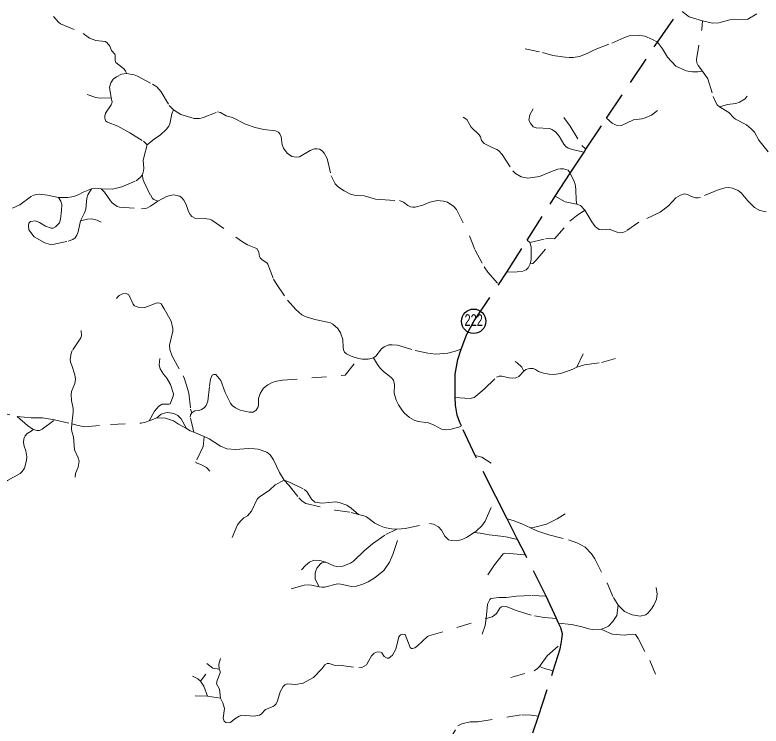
# Model space of a CAD drawing. Extents: x 220.8 to 246.7, y 7287.6 to 7315.8.
# Drawn here: x 238.74 to 243.82, y 7293.59 to 7298.43 of the extents above; entities that cross this region are included whole.
import ezdxf
from ezdxf.enums import TextEntityAlignment as Align

# ---------------------------------------------------------------- set-up
doc = ezdxf.new("R2010")
doc.units = 0
doc.header["$LTSCALE"] = 0.032
for name, pattern in [('DOTTED', [1.5, 0.3, -1.2]), ('LONG_DASHED', [7.5, 6, -1.5]), ('MEDIUM_DASHED', [4.5, 3, -1.5])]:
    doc.linetypes.add(name, pattern=pattern)
for name, color, linetype, lineweight in [('13', 7, 'Continuous', 25), ('4', 7, 'LONG_DASHED', 25), ('6', 7, 'MEDIUM_DASHED', 13), ('7', 7, 'DOTTED', 13)]:
    doc.layers.add(name, color=color, linetype=linetype, lineweight=lineweight)
doc.layers.add('61', color=7, linetype='Continuous')

msp = doc.modelspace()

# ---------------------------------------------------------------- linework, layer by layer
at = {"layer": '13'}
msp.add_circle((241.8611, 7296.3455), 0.083, dxfattribs=at)
at = {"layer": '4'}
msp.add_lwpolyline([(242.2645, 7293.5438), (242.3022, 7293.6576), (242.4029, 7293.9656), (242.4498, 7294.1165), (242.4567, 7294.1518), (242.4624, 7294.1805), (242.4649, 7294.2194), (242.4548, 7294.2595), (242.4398, 7294.2921), (242.4259, 7294.3221), (242.3548, 7294.4756), (242.2129, 7294.7565), (242.1598, 7294.8614), (242.0888, 7295.0017), (242.0123, 7295.1523), (241.8711, 7295.4321), (241.7772, 7295.6332), (241.7658, 7295.6577), (241.7495, 7295.7067), (241.7382, 7295.7757), (241.734, 7295.8278), (241.7344, 7295.9853), (241.7532, 7296.0857), (241.7753, 7296.1551), (241.8147, 7296.2576), (241.8649, 7296.348), (242.031, 7296.5946), (242.0862, 7296.68), (242.225, 7296.8973), (242.4158, 7297.1958), (242.5187, 7297.3535), (242.6137, 7297.4974), (242.626, 7297.516), (242.7662, 7297.7271), (243.1124, 7298.2445), (243.2485, 7298.4414)], dxfattribs=at)
at = {"layer": '6'}
for points in [[(243.2801, 7298.4546), (243.3292, 7298.417), (243.42, 7298.3897)], [(243.42, 7298.3897), (243.4865, 7298.3735), (243.5308, 7298.376), (243.6061, 7298.3965), (243.6389, 7298.4014), (243.7102, 7298.3989), (243.7282, 7298.4014), (243.7905, 7298.4383)], [(243.4199, 7298.0487), (243.3906, 7298.0859), (243.3814, 7298.1042), (243.3782, 7298.127), (243.4141, 7298.3319), (243.42, 7298.3897)], [(243.1124, 7298.2445), (243.1479, 7298.1994), (243.1811, 7298.1427), (243.2372, 7298.082), (243.3071, 7298.05), (243.3521, 7298.0442), (243.3886, 7298.0442), (243.4199, 7298.0487)], [(243.4199, 7298.0487), (243.4565, 7297.9952), (243.493, 7297.8745), (243.5087, 7297.8386), (243.5204, 7297.8184), (243.5357, 7297.8055), (243.598, 7297.7662), (243.632, 7297.7303), (243.645, 7297.7206), (243.72, 7297.6834), (243.7507, 7297.656), (243.7735, 7297.6331), (243.8042, 7297.5783), (243.8877, 7297.4713)], [(240.2175, 7297.7332), (240.3073, 7297.6864), (240.372, 7297.6647), (240.4324, 7297.6514), (240.5115, 7297.6419), (240.5311, 7297.6318), (240.5411, 7297.6202), (240.5496, 7297.6), (240.5565, 7297.5454), (240.5661, 7297.5226), (240.5899, 7297.4897), (240.6223, 7297.4664), (240.6551, 7297.4627), (240.6748, 7297.4653), (240.7464, 7297.5083), (240.7771, 7297.5183), (240.7951, 7297.5199), (240.8121, 7297.5157), (240.8301, 7297.5046), (240.8429, 7297.4902), (240.8641, 7297.4542), (240.8916, 7297.3359), (240.9182, 7297.2819), (240.9404, 7297.258), (240.9786, 7297.2331), (241.0263, 7297.2084), (241.0603, 7297.2023), (241.1149, 7297.2002), (241.1923, 7297.1774), (241.2236, 7297.1732), (241.3567, 7297.1668), (241.3826, 7297.1567), (241.4134, 7297.1339), (241.4304, 7297.1254), (241.4468, 7297.1217), (241.4632, 7297.1223), (241.5147, 7297.1366), (241.5619, 7297.1557), (241.6138, 7297.1679), (241.6557, 7297.1636), (241.6833, 7297.1562), (241.7252, 7297.126), (241.7443, 7297.1058), (241.8323, 7296.9271), (241.8705, 7296.829), (241.9325, 7296.7171), (241.958, 7296.68), (242.031, 7296.5946)], [(239.3238, 7297.2476), (239.4021, 7297.2451), (239.465, 7297.2594), (239.5631, 7297.3023), (239.5898, 7297.3242), (239.6061, 7297.3423), (239.609, 7297.3148), (239.6148, 7297.2962), (239.6598, 7297.2049), (239.674, 7297.1818), (239.6823, 7297.1741), (239.7099, 7297.163)], [(239.0333, 7297.1878), (239.0504, 7297.1628), (239.0555, 7297.1396), (239.0547, 7297.1002), (239.0478, 7297.0411), (239.0401, 7297.0162), (239.0136, 7296.9888), (238.9964, 7296.9802), (238.9827, 7296.9785), (238.945, 7296.9931), (238.9038, 7297.0179), (238.8764, 7297.0282), (238.8439, 7297.0239), (238.8319, 7297.0136), (238.8284, 7296.9982), (238.8327, 7296.9673), (238.867, 7296.9211), (238.9407, 7296.8791), (238.9707, 7296.8696), (238.993, 7296.8671), (239.1001, 7296.8902), (239.1318, 7296.9014), (239.1473, 7296.9142), (239.1575, 7296.9305), (239.1678, 7296.9545), (239.1838, 7297.0297), (239.2115, 7297.083), (239.2201, 7297.1088), (239.2261, 7297.1842), (239.233, 7297.2065), (239.2583, 7297.2465)], [(239.0333, 7297.1878), (239.0983, 7297.1879), (239.1373, 7297.1956), (239.1678, 7297.206), (239.2021, 7297.2251), (239.2583, 7297.2465)], [(239.2583, 7297.2465), (239.284, 7297.2508), (239.3238, 7297.2476)], [(239.3238, 7297.2476), (239.3461, 7297.2245), (239.388, 7297.1645), (239.4001, 7297.1519), (239.4336, 7297.1263), (239.4495, 7297.1216), (239.5999, 7297.1105), (239.6343, 7297.1156), (239.6604, 7297.1291), (239.7099, 7297.163)], [(243.8525, 7297.0897), (243.8094, 7297.0994), (243.7742, 7297.1203), (243.7279, 7297.1653), (243.6822, 7297.2195), (243.662, 7297.2358), (243.6248, 7297.2515), (243.5993, 7297.2554), (243.5726, 7297.2547), (243.5256, 7297.241), (243.4056, 7297.1882), (243.3899, 7297.1849), (243.371, 7297.1856), (243.3442, 7297.194), (243.3175, 7297.2084), (243.2947, 7297.2117), (243.2686, 7297.2038), (243.2385, 7297.1849), (243.187, 7297.1308), (243.1309, 7297.0884), (242.9867, 7297.0192), (242.8986, 7296.9592), (242.8778, 7296.95), (242.8634, 7296.9481), (242.838, 7296.952), (242.7832, 7296.9716), (242.729, 7296.9683), (242.7166, 7296.9709), (242.6996, 7296.9807), (242.6892, 7296.9898), (242.6664, 7297.0218), (242.6188, 7297.1017), (242.5887, 7297.1327), (242.5635, 7297.1424), (242.4837, 7297.1575), (242.4158, 7297.1958)], [(238.721, 7297.1162), (238.7692, 7297.1373), (238.8563, 7297.2006), (238.8839, 7297.2089), (238.903, 7297.2108), (238.9582, 7297.2032), (239.0333, 7297.1878)], [(239.7099, 7297.163), (239.7694, 7297.1943), (239.7936, 7297.2022), (239.8178, 7297.205), (239.8597, 7297.1971), (239.8737, 7297.1859), (239.8877, 7297.1687), (239.904, 7297.1407), (239.9198, 7297.0923), (239.9305, 7297.0723), (239.9426, 7297.0583), (239.9664, 7297.0453), (240.0441, 7297.0429), (240.0627, 7297.0406), (240.0772, 7297.0346), (240.2858, 7296.8865), (240.3203, 7296.8664), (240.3766, 7296.8441), (240.3855, 7296.838), (240.3971, 7296.8143), (240.4018, 7296.7854), (240.4069, 7296.777), (240.418, 7296.7659), (240.4548, 7296.7403), (240.46, 7296.7333), (240.4981, 7296.6313), (240.5154, 7296.602), (240.5922, 7296.4902), (240.6504, 7296.425), (240.6909, 7296.3887), (240.7128, 7296.3775), (240.7789, 7296.3579), (240.8823, 7296.3365), (240.9009, 7296.3267), (240.9349, 7296.2965), (240.9536, 7296.2667), (240.9694, 7296.2224), (240.9717, 7296.168), (240.9754, 7296.1503), (240.9824, 7296.1358), (240.9959, 7296.1232), (241.0267, 7296.1074), (241.0764, 7296.0922)], [(242.0862, 7296.68), (242.1569, 7296.6813), (242.1957, 7296.6867), (242.2185, 7296.6957), (242.2312, 7296.7089), (242.2465, 7296.7354), (242.2519, 7296.7668), (242.253, 7296.8527), (242.2434, 7296.8814), (242.225, 7296.8973)], [(241.0764, 7296.0922), (241.103, 7296.0869), (241.1436, 7296.0874), (241.1787, 7296.0969), (241.1938, 7296.107), (241.2339, 7296.1577), (241.2525, 7296.1717), (241.2833, 7296.1843), (241.307, 7296.1856), (241.3429, 7296.1819), (241.4616, 7296.1475), (241.5645, 7296.1256), (241.6041, 7296.1219), (241.6842, 7296.1284), (241.728, 7296.1391), (241.7753, 7296.1551)], [(239.9564, 7295.5899), (239.9298, 7295.6938), (239.9319, 7295.7095), (239.9415, 7295.723), (239.9613, 7295.7362), (239.9918, 7295.7389), (240.0084, 7295.7453), (240.026, 7295.7555), (240.0389, 7295.7715), (240.0506, 7295.802), (240.0619, 7295.9068), (240.0699, 7295.9512), (240.0795, 7295.9791), (240.0892, 7295.9844), (240.1047, 7295.9833), (240.1384, 7295.9427), (240.1683, 7295.8603), (240.2058, 7295.7876), (240.217, 7295.7731), (240.2384, 7295.7565), (240.2705, 7295.741), (240.3315, 7295.7266), (240.3598, 7295.7277), (240.3801, 7295.741), (240.3903, 7295.7592), (240.3951, 7295.7742), (240.3967, 7295.8207), (240.4063, 7295.8544), (240.4299, 7295.8908), (240.4582, 7295.9133), (240.4893, 7295.9298), (240.5187, 7295.9379), (240.5599, 7295.9443), (240.9856, 7295.978), (241.0764, 7296.0922)], [(238.5163, 7295.728), (238.5444, 7295.7313), (238.6045, 7295.7324), (238.7527, 7295.6978)], [(239.7022, 7295.6875), (239.7337, 7295.7125), (239.7612, 7295.7228), (239.7773, 7295.7254), (239.8196, 7295.7177), (239.8459, 7295.7035), (239.869, 7295.6805), (239.9056, 7295.6163)], [(238.7527, 7295.6978), (238.8464, 7295.6888), (238.9253, 7295.6875), (239.0071, 7295.6752)], [(238.7527, 7295.6978), (238.8235, 7295.6352), (238.8602, 7295.6079), (238.8889, 7295.6013), (238.9047, 7295.6031), (238.9223, 7295.6104), (239.0071, 7295.6752)], [(239.0071, 7295.6752), (239.1248, 7295.6474), (239.1665, 7295.6355), (239.2127, 7295.6272), (239.3879, 7295.6439), (239.597, 7295.6522), (239.6259, 7295.658), (239.6522, 7295.6679), (239.7022, 7295.6875)], [(239.7022, 7295.6875), (239.7619, 7295.6851), (239.8158, 7295.6685), (239.851, 7295.6457), (239.9056, 7295.6163)], [(239.9056, 7295.6163), (239.93, 7295.6009), (239.9564, 7295.5899)], [(239.9564, 7295.5899), (240.0257, 7295.5618), (240.0596, 7295.5457), (240.1366, 7295.4957), (240.1808, 7295.4784), (240.2424, 7295.4739), (240.3252, 7295.479), (240.3695, 7295.4784), (240.3926, 7295.4758), (240.4535, 7295.4546), (240.474, 7295.436), (240.4984, 7295.4033), (240.5388, 7295.3173), (240.5711, 7295.2643)], [(240.5711, 7295.2643), (240.6023, 7295.2307), (240.671, 7295.1441), (240.6928, 7295.1223), (240.7185, 7295.1062), (240.918, 7295.0594), (241.0277, 7295.044), (241.0773, 7295.0311)], [(240.5711, 7295.2643), (240.6105, 7295.2494), (240.7075, 7295.2002), (240.7244, 7295.1863), (240.7575, 7295.1348), (240.7795, 7295.1142), (240.8266, 7295.1084), (240.9214, 7295.1164), (240.9456, 7295.1113), (240.9963, 7295.0929), (241.0272, 7295.0731), (241.0773, 7295.0311)], [(241.0773, 7295.0311), (241.1137, 7295.0216), (241.1304, 7295.0139), (241.1887, 7294.9715), (241.2202, 7294.9548), (241.2548, 7294.9414), (241.301, 7294.9324), (241.3377, 7294.9309), (241.3668, 7294.9319), (241.394, 7294.9343), (241.5609, 7294.9696), (241.5878, 7294.9657), (241.6218, 7294.9459), (241.6411, 7294.9247), (241.6648, 7294.8836), (241.6898, 7294.858), (241.7103, 7294.8528), (241.7431, 7294.8515), (241.7751, 7294.8592), (241.8117, 7294.8746), (241.8633, 7294.9073), (241.8791, 7294.917), (241.9156, 7294.9536), (241.94, 7294.9856), (242.0123, 7295.1523)], [(240.1622, 7293.625), (240.1743, 7293.6149), (240.1992, 7293.6135), (240.208, 7293.6176), (240.2349, 7293.6405), (240.2638, 7293.658), (240.2827, 7293.6654), (240.3634, 7293.658), (240.4031, 7293.6647), (240.4132, 7293.6707), (240.4441, 7293.7024), (240.4946, 7293.7246), (240.5074, 7293.7326), (240.5161, 7293.7427), (240.5262, 7293.7616), (240.5424, 7293.8235), (240.5639, 7293.8611), (240.576, 7293.8719), (240.5942, 7293.8786), (240.648, 7293.8726), (240.6998, 7293.8834), (240.7698, 7293.921), (240.8263, 7293.9796), (240.8485, 7294.0078), (240.8633, 7294.0166), (240.8768, 7294.0172), (240.9171, 7294.0038), (240.9427, 7294.0058), (241.078, 7293.987), (241.1002, 7293.989), (241.1311, 7294.0078), (241.1647, 7294.0691), (241.1843, 7294.0872), (241.2051, 7294.096), (241.2266, 7294.0939), (241.2347, 7294.0886), (241.2515, 7294.0637), (241.2717, 7294.0522), (241.2832, 7294.0529), (241.3081, 7294.0724), (241.3316, 7294.1135), (241.3511, 7294.1982), (241.3626, 7294.211), (241.3753, 7294.2157), (241.3935, 7294.213), (241.4285, 7294.1262), (241.4366, 7294.1195), (241.4453, 7294.1182), (241.4608, 7294.1229), (241.479, 7294.1363), (241.5462, 7294.2003), (241.5557, 7294.2043), (241.9456, 7294.3217), (241.987, 7294.3342), (242.0038, 7294.3449), (242.0172, 7294.357), (242.0401, 7294.394), (242.0495, 7294.4021), (242.0663, 7294.4075), (242.0818, 7294.4055), (242.1572, 7294.3738), (242.2756, 7294.3402), (242.3402, 7294.3301), (242.4259, 7294.3221)]]:
    msp.add_lwpolyline(points, dxfattribs=at)
at = {"layer": '7'}
for p, q in [((242.5637, 7296.0338), (242.6231, 7296.1619)), ((240.0375, 7293.9441), (239.9996, 7293.8959)), ((239.9637, 7293.7959), (240.0486, 7293.7931)), ((240.0486, 7293.7931), (240.1362, 7293.7812))]:
    msp.add_line(p, q, dxfattribs=at)
for points in [[(238.9985, 7298.4192), (239.0332, 7298.3818), (239.0477, 7298.3704), (239.2022, 7298.3035), (239.2458, 7298.2724), (239.2883, 7298.2558), (239.3511, 7298.2491), (239.3625, 7298.2424), (239.3827, 7298.218), (239.3946, 7298.1874), (239.4169, 7298.163), (239.42, 7298.1558), (239.42, 7298.1205), (239.4231, 7298.106), (239.4771, 7298.065), (239.489, 7298.05), (239.4968, 7298.0313)], [(242.2114, 7298.1988), (242.3301, 7298.1737), (242.4012, 7298.1545), (242.5066, 7298.14), (242.5376, 7298.14), (242.582, 7298.148), (242.6344, 7298.1689), (242.6879, 7298.1956), (242.8023, 7298.2384), (242.8847, 7298.2753), (242.9205, 7298.2881), (242.9777, 7298.2924), (243.0269, 7298.286), (243.0783, 7298.2641), (243.1124, 7298.2445)], [(239.393, 7297.8664), (239.3822, 7297.9234), (239.3818, 7297.9386), (239.3896, 7297.9679), (239.4051, 7297.9922), (239.4277, 7298.0101), (239.4638, 7298.0266), (239.4968, 7298.0313)], [(239.4968, 7298.0313), (239.5496, 7298.023), (239.5719, 7298.0137), (239.6741, 7297.9592), (239.7036, 7297.9401), (239.7322, 7297.9079), (239.7882, 7297.8145), (239.8162, 7297.7835)], [(239.2294, 7297.8897), (239.2881, 7297.8691), (239.3184, 7297.8644), (239.393, 7297.8664)], [(239.393, 7297.8664), (239.398, 7297.8371), (239.393, 7297.8192), (239.3545, 7297.7615), (239.3488, 7297.7413), (239.3484, 7297.7285), (239.3538, 7297.7103), (239.3663, 7297.7005), (239.4388, 7297.6742), (239.5191, 7297.629), (239.6115, 7297.5703), (239.6381, 7297.5461)], [(243.5357, 7297.8055), (243.5896, 7297.8204), (243.6463, 7297.8282), (243.6724, 7297.836), (243.7089, 7297.8589), (243.7246, 7297.8778)], [(239.6381, 7297.5461), (239.6873, 7297.5875), (239.7258, 7297.6128), (239.7693, 7297.6519), (239.7851, 7297.6739), (239.7919, 7297.689), (239.805, 7297.7578), (239.8162, 7297.7835)], [(239.8162, 7297.7835), (239.867, 7297.7518), (239.9567, 7297.7264), (239.995, 7297.7249), (240.0132, 7297.729), (240.1174, 7297.77), (240.1361, 7297.7669), (240.1745, 7297.7425), (240.2175, 7297.7332)], [(242.2652, 7297.7903), (242.2443, 7297.7502), (242.2371, 7297.7149), (242.2474, 7297.6927), (242.2673, 7297.6687), (242.2875, 7297.6611), (242.379, 7297.6563), (242.3937, 7297.6515), (242.4188, 7297.6347), (242.4424, 7297.6042), (242.475, 7297.5518), (242.4887, 7297.5354), (242.5055, 7297.5234), (242.5418, 7297.5124), (242.6137, 7297.4974)], [(242.7662, 7297.7271), (242.8031, 7297.693), (242.8326, 7297.68), (242.868, 7297.6777), (242.9493, 7297.7154), (243.0059, 7297.7242), (243.0283, 7297.7307), (243.0719, 7297.749), (243.1125, 7297.7802)], [(241.7906, 7297.7349), (241.8146, 7297.7182), (241.8438, 7297.6654), (241.898, 7297.614), (241.9072, 7297.6002), (241.9146, 7297.5766), (241.9317, 7297.5543), (241.9864, 7297.5275), (242.0197, 7297.5155), (242.0294, 7297.5081), (242.0553, 7297.4807), (242.128, 7297.3697), (242.1451, 7297.3507), (242.1835, 7297.3289), (242.2294, 7297.3187), (242.3099, 7297.3303), (242.3904, 7297.3655), (242.434, 7297.3803), (242.4525, 7297.3831), (242.4728, 7297.3835), (242.5048, 7297.3734), (242.5187, 7297.3535), (242.5464, 7297.297), (242.552, 7297.278), (242.5575, 7297.2442), (242.5589, 7297.1683), (242.5635, 7297.1424)], [(242.476, 7297.7331), (242.5178, 7297.6724), (242.5977, 7297.5412), (242.626, 7297.516)], [(239.6381, 7297.5461), (239.6163, 7297.4684), (239.6112, 7297.4388), (239.6146, 7297.3872), (239.6134, 7297.369), (239.6061, 7297.3423)], [(242.4114, 7296.9075), (242.5167, 7297.0268), (242.5607, 7297.0639), (242.6188, 7297.1017)], [(239.1838, 7297.0297), (239.2309, 7297.041), (239.2577, 7297.0422), (239.2971, 7297.0339), (239.3242, 7297.0197)], [(242.2434, 7296.8814), (242.3495, 7296.9063), (242.3867, 7296.91), (242.4114, 7296.9075)], [(242.2465, 7296.7354), (242.2636, 7296.7392), (242.2864, 7296.7609), (242.4114, 7296.9075)], [(239.4297, 7296.5), (239.4366, 7296.5123), (239.447, 7296.52), (239.4698, 7296.5318), (239.4953, 7296.5346), (239.5116, 7296.5259), (239.543, 7296.4627), (239.5521, 7296.4513), (239.5617, 7296.4454), (239.5771, 7296.4413), (239.6213, 7296.44), (239.7059, 7296.4709), (239.7232, 7296.4682), (239.7322, 7296.4636), (239.7541, 7296.4304), (239.8018, 7296.3458), (239.8119, 7296.2958), (239.8123, 7296.278), (239.7905, 7296.1829), (239.7914, 7296.1538), (239.8078, 7296.1083), (239.8824, 7295.9737), (239.891, 7295.9528), (239.9128, 7295.8882), (239.9201, 7295.8568), (239.9329, 7295.7481), (239.9415, 7295.723)], [(239.188, 7296.2819), (239.1905, 7296.2458), (239.1863, 7296.2329), (239.1277, 7296.1466), (239.1197, 7296.1257), (239.1122, 7296.0867), (239.1143, 7296.067), (239.1252, 7296.0436), (239.1453, 7295.982), (239.1503, 7295.9506), (239.144, 7295.9209), (239.1222, 7295.8681), (239.1197, 7295.8471), (239.1231, 7295.8057), (239.1331, 7295.7508), (239.1335, 7295.7274), (239.1248, 7295.6474), (239.1222, 7295.6139), (239.1243, 7295.595), (239.1365, 7295.559), (239.1415, 7295.4706), (239.167, 7295.417), (239.1742, 7295.3944), (239.1679, 7295.3517), (239.149, 7295.3086), (239.1478, 7295.2847)], [(239.6522, 7295.6679), (239.6864, 7295.7348), (239.7169, 7295.7689), (239.7386, 7295.7803), (239.7863, 7295.7808), (239.7951, 7295.7844), (239.8142, 7295.8367), (239.8163, 7295.8512), (239.7956, 7295.9144), (239.7723, 7295.9573), (239.748, 7295.9863), (239.7262, 7296.0225), (239.7195, 7296.0474), (239.7247, 7296.0929)], [(241.1787, 7296.0969), (241.2058, 7296.0517), (241.2251, 7296.0269), (241.2461, 7296.0045), (241.2993, 7295.9633), (241.3153, 7295.9436), (241.3212, 7295.9147), (241.3194, 7295.857), (241.3332, 7295.8089), (241.3487, 7295.7769), (241.3753, 7295.7366), (241.3899, 7295.7192), (241.4238, 7295.6912), (241.4568, 7295.6729), (241.4834, 7295.6633), (241.5525, 7295.6546), (241.5914, 7295.6386), (241.6418, 7295.6116), (241.6775, 7295.6074), (241.6986, 7295.6093), (241.7591, 7295.6248), (241.7772, 7295.6332)], [(242.1443, 7296.0714), (242.1573, 7296.0634), (242.1892, 7296.0324), (242.2027, 7296.007)], [(242.5637, 7296.0338), (242.6155, 7296.0483), (242.7317, 7296.0642), (242.8499, 7296.099)], [(242.2027, 7296.007), (242.2156, 7296.0164), (242.2315, 7296.0223), (242.2432, 7296.0248), (242.2663, 7296.0232), (242.2818, 7296.0181), (242.3028, 7296.0034), (242.3372, 7295.9917), (242.3745, 7295.985), (242.4076, 7295.9829), (242.4516, 7295.9904), (242.4935, 7296.0039), (242.5363, 7296.0185), (242.5637, 7296.0338)], [(241.734, 7295.8278), (241.8361, 7295.8206), (241.8634, 7295.8278), (241.8768, 7295.8357), (241.9326, 7295.884), (242.017, 7295.9649), (242.0346, 7295.9709), (242.0537, 7295.972), (242.1038, 7295.9599), (242.1287, 7295.9586), (242.1489, 7295.9615), (242.1682, 7295.9703), (242.2027, 7296.007)], [(238.5608, 7294.6938), (238.5812, 7294.7289), (238.6029, 7294.7992), (238.615, 7294.8686), (238.6237, 7295.1471), (238.6272, 7295.1849), (238.6315, 7295.2001), (238.6515, 7295.2348), (238.6632, 7295.2474), (238.6857, 7295.263), (238.7716, 7295.3094), (238.7851, 7295.3229), (238.8011, 7295.3459), (238.815, 7295.3988), (238.8172, 7295.4227), (238.8111, 7295.4639), (238.7994, 7295.4947), (238.7959, 7295.5194), (238.7981, 7295.5463), (238.8064, 7295.5663), (238.8202, 7295.5823), (238.8484, 7295.5979), (238.8602, 7295.6079)], [(240.0257, 7295.5618), (240.0184, 7295.4926), (239.9693, 7295.3891), (239.9721, 7295.3815), (240.002, 7295.3717), (240.0423, 7295.351), (240.0652, 7295.3248)], [(241.8711, 7295.4321), (241.9158, 7295.4201), (241.9791, 7295.3809)], [(240.2163, 7294.8751), (240.252, 7294.9599), (240.2729, 7294.9857), (240.2968, 7295.0073), (240.3203, 7295.0224), (240.3486, 7295.0522), (240.3875, 7295.1341), (240.4011, 7295.1491), (240.4695, 7295.1969), (240.5095, 7295.2318), (240.5711, 7295.2643)], [(242.0888, 7295.0017), (242.1311, 7294.9895), (242.1883, 7294.9674), (242.247, 7294.9394)], [(242.247, 7294.9394), (242.2765, 7294.9433), (242.3574, 7294.9653), (242.4289, 7295.0008), (242.4832, 7295.0359)], [(240.8082, 7294.5392), (240.8279, 7294.5356), (240.8452, 7294.5366), (240.9335, 7294.5578), (240.9557, 7294.5572), (241.0292, 7294.5411), (241.0626, 7294.5438), (241.106, 7294.5558), (241.1436, 7294.5719), (241.1907, 7294.6013), (241.2495, 7294.6487), (241.2877, 7294.7062), (241.3103, 7294.7594), (241.3668, 7294.9319)], [(240.8543, 7294.7057), (240.908, 7294.6817), (240.9292, 7294.6777), (240.9691, 7294.679), (241.0211, 7294.699), (241.0433, 7294.714), (241.1148, 7294.7839), (241.173, 7294.832), (241.2635, 7294.8944), (241.3377, 7294.9309)], [(241.8633, 7294.9073), (241.9062, 7294.9046), (241.9662, 7294.8928), (242.0699, 7294.8807), (242.1598, 7294.8614)], [(242.247, 7294.9394), (242.2906, 7294.9186), (242.3734, 7294.8919), (242.5067, 7294.8573), (242.5707, 7294.8352), (242.6205, 7294.809), (242.6646, 7294.7623), (242.6861, 7294.7277), (242.7711, 7294.5651), (242.8126, 7294.4654), (242.8446, 7294.4124)], [(241.9573, 7294.6203), (242.004, 7294.689), (242.061, 7294.763), (242.071, 7294.7674), (242.1078, 7294.7659), (242.2129, 7294.7565)], [(240.6894, 7294.6539), (240.7158, 7294.6836), (240.7426, 7294.7068), (240.772, 7294.7192), (240.8135, 7294.7183), (240.8543, 7294.7057)], [(240.8082, 7294.5392), (240.7825, 7294.5915), (240.7822, 7294.6313), (240.7861, 7294.6467), (240.792, 7294.6647), (240.8171, 7294.6954), (240.8263, 7294.7006), (240.8543, 7294.7057)], [(240.6191, 7294.5245), (240.707, 7294.549), (240.7338, 7294.5516), (240.7567, 7294.5503), (240.8082, 7294.5392)], [(242.8446, 7294.4124), (242.8886, 7294.3694), (242.9395, 7294.3473), (242.9951, 7294.3384), (243.0345, 7294.3484), (243.0492, 7294.3604), (243.0728, 7294.3893), (243.088, 7294.4145), (243.1063, 7294.4549), (243.11, 7294.4885), (243.1042, 7294.533)], [(241.9178, 7294.2159), (241.9397, 7294.275), (241.9456, 7294.3217), (241.9563, 7294.4198), (241.9713, 7294.4521), (241.9772, 7294.4583), (242.0313, 7294.4656), (242.0831, 7294.4663), (242.1522, 7294.4739), (242.2605, 7294.4795), (242.3548, 7294.4756)], [(242.7286, 7294.2512), (242.7459, 7294.2545), (242.7795, 7294.2707), (242.8099, 7294.3027), (242.8351, 7294.3437), (242.8446, 7294.4124)], [(242.4398, 7294.2921), (242.5266, 7294.2828), (242.6006, 7294.2671), (242.6445, 7294.2524), (242.6709, 7294.2487), (242.7286, 7294.2512)], [(242.7286, 7294.2512), (242.7874, 7294.223), (242.8068, 7294.2167), (242.886, 7294.2099), (242.9416, 7294.2167), (242.9626, 7294.2146), (242.982, 7294.1873), (243.0597, 7294.0362), (243.109, 7293.9245)], [(242.3092, 7293.997), (242.3608, 7294.0686), (242.4567, 7294.1518)], [(240.1377, 7294.0494), (240.1256, 7294.0119), (240.1276, 7293.9768)], [(240.0429, 7294.0168), (240.0852, 7293.9839), (240.1276, 7293.9768)], [(242.1142, 7293.9206), (242.2726, 7293.9669), (242.2951, 7293.9816), (242.3092, 7293.997)], [(242.3092, 7293.997), (242.3438, 7293.9826), (242.4029, 7293.9656)], [(240.1276, 7293.9768), (240.1336, 7293.9619), (240.1336, 7293.9525), (240.1131, 7293.9003), (240.1104, 7293.878), (240.131, 7293.8428), (240.1362, 7293.7812)], [(239.9473, 7293.9303), (239.9822, 7293.9117), (239.9996, 7293.8959)], [(239.9996, 7293.8959), (240.0233, 7293.8624), (240.0486, 7293.7931)], [(240.1362, 7293.7812), (240.1524, 7293.7477), (240.1631, 7293.7107), (240.1551, 7293.6447), (240.1622, 7293.625)], [(241.686, 7293.4803), (241.7526, 7293.5915), (241.7794, 7293.606), (241.8378, 7293.6188), (241.8887, 7293.6199), (242.1913, 7293.6681), (242.2523, 7293.6654), (242.3022, 7293.6576)]]:
    msp.add_lwpolyline(points, dxfattribs=at)

# ---------------------------------------------------------------- texts
at = {"layer": '61', "width": 0.7}
msp.add_text('222', height=0.08, dxfattribs=at).set_placement((241.8611, 7296.3131), align=Align.CENTER)

doc.saveas('drawing.dxf')
